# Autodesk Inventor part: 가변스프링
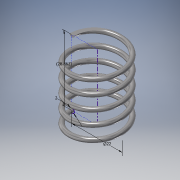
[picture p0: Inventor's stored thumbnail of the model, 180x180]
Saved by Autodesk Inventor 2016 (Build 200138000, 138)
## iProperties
Created: 2015-11
Part Number: 가변스프링
Material: 스테인레스 스틸
Document SubType Name: Modeling
Designer: eco
Density: 8 g/cm^3
Appearance: 반연마
Mass: 8.55949 g
Surface Area: 21.6802 cm^2
Volume: 1.06994 cm^3
Author: eco
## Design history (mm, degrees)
sketch "스케치1"
  geometry: L1 (0, 0)-(11, 0); L2 (11, 0)-(11, 29.223); L3 (11, 29.223)-(0, 29.223); L4 (0, 29.223)-(0, 0); C1 r 1 at (11, 0)
  constraints: 8 end point, 2 parallel, 1 centre point, 1 coincident, 1 horizontal, 1 perpendicular
  dimensions: "d0" = 2 diameter of C1; "d1" = 22 diameter of L2 L4; "d2" = 29.22346 distance of L1.end L2.end (derived)
feature "코일1" pitch "d3" = 10; turns "d5" = 5; dims "d4" = 29.22346 (= d2), "d6" = 0, angle "d7" = 90 deg, angle "d8" = 90 deg, "d9" = 0, "d10" = 0
sketch "스케치2"
  geometry: L1 (-12, 0)-(-10, 0) reference; 1 further point
  constraints: 1 horizontal alignment
extrude "돌출1" cut sketch "스케치2" stored distance "d11" = 10; taper "d12" = 0 deg
node "작업 평면1"
sketch "스케치3"
  geometry: L1 (1, 0)-(-1, 0) reference; 1 further point
  constraints: 1 horizontal alignment
extrude "돌출2" cut sketch "스케치3" stored distance "d14" = 10; taper "d15" = 0 deg
node "솔리드1"
node "절단 모서리 투영1"
node "절단 모서리 투영2"
other parameters: "d13" = 0
